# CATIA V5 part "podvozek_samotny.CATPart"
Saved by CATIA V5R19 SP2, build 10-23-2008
Part number: podvozek_samotny
Bounding box of the stored display mesh (mm): x -1700 to 1700, y -40 to 2280, z 0 to 2265.495
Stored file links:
  C:\Users\Martiin\Desktop\9.semestr\Projekt-diplomka\3D model\podvozek_samotny.CATPart
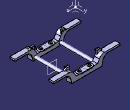
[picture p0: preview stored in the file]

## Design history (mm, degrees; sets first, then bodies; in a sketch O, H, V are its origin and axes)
Body1 (main body)
  Sketch1 on zx-plane, origin (0, 0, 0), H (-1, 0, 0), V (0, 0, 1)
    line L1 (-905.2897, 550) -> (-1700, 550)
    point P1 (-1700, 550)
    line L2 (-1700, 550) -> (-1700, 455)
    point P2 (-1700, 455)
    line L3 (-1700, 455) -> (-1111.8423, 455)
    point P3 (-770, 0)
    line L4 (-770, 0) -> (0, 0)
    line L5 (0, 220) -> (-550, 220)
    point P4 (0, 220)
    point P5 (-550, 220)
    construction line L6 (0, 66.1363) -> (0, -42.4343)
    point P6 (0, 66.1363)
    arc A1 centre (-1111.8423, 155) radius 300 from (-1111.8423, 455) to (-819.0086, 220.1801) cw
    point P8 (-1111.8423, 455)
    arc A2 centre (-905.2897, 250) radius 300 from (-905.2897, 550) to (-640.1272, 390.317) cw
    point P10 (-905.2897, 550)
    line L7 (-640.1272, 390.317) -> (-550, 220)
    point P12 (-550, 220)
    point P13 (-640.1272, 390.317)
    line L8 (-819.0086, 220.1801) -> (-770, 0)
    point P14 (-770, 0)
    point P15 (-819.0086, 220.1801)
    point P16 (1700, 550)
    point P17 (1700, 455)
    point P18 (770, 0)
    point P19 (550, 220)
    point P20 (1111.8423, 455)
    point P22 (905.2897, 550)
    point P24 (550, 220)
    point P25 (640.1272, 390.317)
    point P26 (770, 0)
    point P27 (819.0086, 220.1801)
    line L9 (905.2897, 550) -> (1700, 550)
    line L10 (1700, 550) -> (1700, 455)
    line L11 (1700, 455) -> (1111.8423, 455)
    arc A3 centre (1111.8423, 155) radius 300 from (1111.8423, 455) to (819.0086, 220.1801) ccw
    arc A4 centre (905.2897, 250) radius 300 from (905.2897, 550) to (640.1272, 390.317) ccw
    line L12 (640.1272, 390.317) -> (550, 220)
    line L13 (819.0086, 220.1801) -> (770, 0)
    point P28 (0, 220)
    line L14 (0, 220) -> (550, 220)
    point P29 (0, 0)
    line L15 (770, 0) -> (0, 0)
    line L16 (1690, 540) -> (1690, 465)
    line L17 (1690, 465) -> (1111.8423, 465)
    arc A5 centre (1111.8423, 155) radius 310 from (1111.8423, 465) to (809.2475, 222.3528) ccw
    line L18 (809.2475, 222.3528) -> (761.9811, 10)
    line L19 (761.9811, 10) -> (0, 10)
    line L20 (-761.9811, 10) -> (0, 10)
    line L21 (-809.2475, 222.3528) -> (-761.9811, 10)
    arc A6 centre (-1111.8423, 155) radius 310 from (-809.2475, 222.3528) to (-1111.8423, 465) ccw
    line L22 (-1690, 465) -> (-1111.8423, 465)
    line L23 (-1690, 540) -> (-1690, 465)
    line L24 (-905.2897, 540) -> (-1690, 540)
    arc A7 centre (-905.2897, 250) radius 290 from (-648.966, 385.6397) to (-905.2897, 540) ccw
    line L25 (-648.966, 385.6397) -> (-556.0221, 210)
    line L26 (0, 210) -> (-556.0221, 210)
    line L27 (0, 210) -> (556.0221, 210)
    line L28 (648.966, 385.6397) -> (556.0221, 210)
    arc A8 centre (905.2897, 250) radius 290 from (905.2897, 540) to (648.966, 385.6397) ccw
    line L29 (905.2897, 540) -> (1690, 540)
    distance L5 L4 = 220
    distance L6 L2 = 1700
    distance L4 L1 = 550
    distance L1 L3 = 95
    radius A1 = 300
    radius A2 = 300
    distance P14 V = 770
    distance P12 V = 550
    distance L9 L29 = 10
    horizontal: L1 H, L3 H, L4 H, L5 H
    vertical: L2 V, L6 V
    coincidence: P3 H, P4 V, P6 V, O P29, P4 P28
    tangency: A1 L3, A2 L1, L7 A2, L8 A1
    symmetry: P1 P16 V, P2 P17 V, P3 P18 V, P5 P19 V, P8 P20 V, P10 P22 V, P12 P24 V, P13 P25 V, P14 P26 V, P15 P27 V, L1 L9 V, L2 L10 V, L3 L11 V, A1 A3 V, A2 A4 V, L7 L12 V, L8 L13 V, P4 P28 V, L5 L14 V, O P29 V, L4 L15 V
  Pad1: profile Sketch1, direction (0, 1, 0), length 250
  Sketch2 on end face of Pad1, origin (0, 250, 0), H (-1, 0, 0), V (0, 0, 1)
    circle A1 centre (-650, 110) radius 85
    point P1 (-650, 110)
    reference projected line E1 (-770, 0) -> (0, 0) from edge [face of Pad1 from Sketch1.L4 | end face of Pad1]
    circle A2 centre (-650, 110) radius 70
    circle A3 centre (650, 110) radius 85
    circle A4 centre (650, 110) radius 70
    radius A1 = 85
    distance P1 E1 = 110
    distance P1 V = 650
    radius A2 = 70
    symmetry: A1 A3 V, A2 A4 V
  Pad2: profile Sketch2, direction (0, 1, 0), length 870
  Plane1: type Offset, RefPlane end face of Pad2, Offset 0, reversed
  Mirror1: of the body so far, about Plane1
  Sketch3 on end face of Pad1, origin (0, 250, 0), H (-1, 0, 0), V (0, 0, 1)
    line L1 (-865, 650) -> (-700, 650)
    line L2 (-700, 650) -> (-700, 468.7604)
    line L3 (-965, 550) -> (-865, 650)
    point P2 (-865, 650)
    reference projected line E1 (-770, 0) -> (0, 0) from edge [face of Pad1 from Sketch1.L4 | end face of Pad1]
    arc A1 centre (-905.2897, 250) radius 300 from (-700, 468.7604) to (-905.2897, 550) ccw
    reference projected arc E2 centre (-905.2897, 250) radius 300 from (-640.1272, 390.317) to (-905.2897, 550) ccw from edge [face of Mirror1 | face of Mirror1]
    line L4 (-965, 550) -> (-905.2897, 550)
    reference projected line E3 (-905.2897, 550) -> (-1700, 550) from edge [face of Mirror1 | face of Mirror1]
    angle L3 L1 = 135
    distance E1 L1 = 650
    distance L2 V = 700
    distance P2 L2 = 165
    horizontal: L1 H, L4 H
    vertical: L2 V
    coincidence: A1 E2, L4 E3
  Pad3: profile Sketch3, direction (0, -1, 0), length 70
  Sketch4 on face of Pad3 from Sketch3.L1, origin (0, 0, 650), H (1, 0, 0), V (0, 1, 0)
    construction line L1 (782.5, 324.4689) -> (782.5, 215.9945)
    point P3 (835, 250)
    line L2 (835, 250) -> (865, 250)
    line L3 (865, 250) -> (865, 300)
    line L4 (865, 300) -> (835, 300)
    line L5 (835, 300) -> (835, 250)
    point P4 (865, 250)
    point P5 (865, 300)
    point P6 (835, 300)
    reference projected line E1 (865, 250) -> (865, 180) from edge [face of Pad3 from Sketch3.L1 | face of Pad3 from Sketch3.L3]
    reference projected line E2 (700, 250) -> (780, 250) from edge [face of Pad3 from Sketch3.L1 | start face of Pad3]
    point P7 (730, 250)
    point P8 (700, 250)
    point P9 (700, 300)
    point P10 (730, 300)
    line L6 (730, 250) -> (700, 250)
    line L7 (700, 250) -> (700, 300)
    line L8 (700, 300) -> (730, 300)
    line L9 (730, 300) -> (730, 250)
    construction line L10 (850, 313.9757) -> (850, 224.2203)
    distance L4 L2 = 50
    distance L5 L3 = 30
    distance L3 L1 = 82.5
    distance L10 L3 = 15
    vertical: L1 V, L3 V, L5 V, L10 V
    horizontal: L2 H, L4 H
    coincidence: L3 E1, L2 E2
    symmetry: P3 P7 L1, P4 P8 L1, P5 P9 L1, P6 P10 L1, L2 L6 L1, L3 L7 L1, L4 L8 L1, L5 L9 L1
  Pad4: profile Sketch4, direction (0, 0, -1), length 40
  Mirror2: of Pad3, Pad4, about yz-plane
  Mirror3: of the body so far, about Plane1
  Sketch5 on face of Pad4 from Sketch4.L4, origin (848.3876, 300, 627.8501), H (1, 0, 0), V (0, 0, -1)
    point P1 (1.6124, -2.1499)
    reference projected line E1 (16.6124, -22.1499) -> (-13.3876, -22.1499) from edge [face of Pad4 from Sketch4.L4 | start face of Pad4]
    reference projected line E2 (-13.3876, -22.1499) -> (-13.3876, 17.8501) from edge [face of Pad4 from Sketch4.L4 | face of Pad4 from Sketch4.L5]
    distance P1 E1 = 20
    distance P1 E2 = 15
  Hole1: placed by Sketch5, at (850, 300, 630) direction (0, -1, 0), diameter 20, depth 30
  Sketch6 on face of Pad4 from Sketch4.L8, origin (718.7731, 300, 635.0308), H (1, 0, 0), V (0, 0, -1)
    point P1 (-3.7731, 5.0308)
    reference projected line E1 (-18.7731, -14.9692) -> (146.2269, -14.9692) from edge [face of Mirror3 | face of Mirror3]
    reference projected line E2 (-18.7731, -14.9692) -> (-18.7731, 25.0308) from edge [face of Pad4 from Sketch4.L8 | face of Pad4]
    distance P1 E1 = 20
    distance E2 P1 = 15
  Hole2: placed by Sketch6, at (715, 300, 630) direction (0, -1, 0), diameter 20, depth 30
  Sketch7 on face of Mirror2, origin (-718.919, 300, 634.1562), H (1, 0, 0), V (0, 0, -1)
    point P1 (3.919, 4.1562)
    reference projected line E1 (-11.081, -15.8438) -> (-11.081, 24.1562) from edge [face of Mirror2 | face of Mirror2]
    reference projected line E2 (-11.081, 24.1562) -> (18.919, 24.1562) from edge [face of Mirror2 | face of Mirror2]
    distance P1 E1 = 15
    distance P1 E2 = 20
  Hole3: placed by Sketch7, at (-715, 300, 630) direction (0, -1, 0), diameter 20, depth 30
  Sketch8 on face of Mirror2, origin (-843.8724, 300, 638.1702), H (1, 0, 0), V (0, 0, -1)
    point P1 (-6.1276, 8.1702)
    reference projected line E1 (-21.1276, -11.8298) -> (-21.1276, 28.1702) from edge [face of Mirror2 | face of Mirror2]
    reference projected line E2 (-21.1276, 28.1702) -> (8.8724, 28.1702) from edge [face of Mirror2 | face of Mirror2]
    distance P1 E1 = 15
    distance P1 E2 = 20
  Hole4: placed by Sketch8, at (-850, 300, 630) direction (0, -1, 0), diameter 20, depth 30
  Mirror4: of Hole1, Hole2, Hole3, Hole4, about Plane1
  Sketch9 on face of Mirror3, origin (0, 0, 10), H (1, 0, 0), V (0, 1, 0)
    point P1 (-761.9811, 10)
    line L1 (-761.9811, 10) -> (761.9811, 10)
    line L2 (761.9811, 10) -> (761.9811, 0)
    line L3 (761.9811, 0) -> (-761.9811, 0)
    line L4 (-761.9811, 0) -> (-761.9811, 10)
    point P2 (761.9811, 10)
    point P3 (761.9811, 0)
    point P4 (-761.9811, 0)
    reference projected line E1 (-761.9811, 0) -> (-761.9811, 250) from edge [face of Mirror3 | face of Mirror3]
    reference projected line E2 (0, 0) -> (-761.9811, 0) from edge [face of Mirror3 | face of Mirror3]
    reference projected line E3 (761.9811, 0) -> (761.9811, 250) from edge [face of Mirror3 | face of Mirror3]
    construction line L5 (-830, 125) -> (-480, 125)
    point P7 (0, 250)
    construction line L6 through (0, 250) direction (1, 0)
    point P10 (-761.9811, 240)
    point P11 (761.9811, 240)
    point P12 (761.9811, 250)
    point P13 (-761.9811, 250)
    line L7 (-761.9811, 240) -> (761.9811, 240)
    line L8 (761.9811, 240) -> (761.9811, 250)
    line L9 (761.9811, 250) -> (-761.9811, 250)
    line L10 (-761.9811, 250) -> (-761.9811, 240)
    distance L1 L3 = 10
    distance L5 L3 = 125
    horizontal: L1 H, L3 H, L5 H
    vertical: L2 V, L4 V
    coincidence: E1 L4, E2 L3, L2 E3
    symmetry: O P7 L5, H L6 L5, P1 P10 L5, P2 P11 L5, P3 P12 L5, P4 P13 L5, L1 L7 L5, L2 L8 L5, L3 L9 L5, L4 L10 L5
  Pad5: profile Sketch9, direction (0, 0, 1), up to the existing solid (limit type 2)
  Pad6: profile face of Pad5 from Sketch9.L8, direction along face of Pad5 from Sketch9.L8, up to the existing solid (limit type 3)
  Pad7: profile face of Pad5 from Sketch9.L2, direction along face of Pad5 from Sketch9.L2, up to the existing solid (limit type 3)
  Pad8: profile face of Pad7, direction along face of Pad7, up to the existing solid (limit type 3)
  Pad9: profile face of Pad6, direction along face of Pad6, up to the existing solid (limit type 3)
  Pad10: profile face of Pad5 from Sketch9.L4, direction along face of Pad5 from Sketch9.L4, up to the existing solid (limit type 3)
  Pad11: profile face of Pad10, direction along face of Pad10, up to the existing solid (limit type 3)
  Pad12: profile face of Pad5 from Sketch9.L10, direction along face of Pad5 from Sketch9.L10, up to the existing solid (limit type 3)
  Pad13: profile face of Pad12, direction along face of Pad12, up to the existing solid (limit type 3)
  Sketch10 on face of Mirror3, origin (0, 0, 10), H (1, 0, 0), V (0, 1, 0)
    point P1 (-761.9811, 2240)
    line L1 (-761.9811, 2240) -> (761.9811, 2240)
    line L2 (761.9811, 2240) -> (761.9811, 2230)
    line L3 (761.9811, 2230) -> (-761.9811, 2230)
    line L4 (-761.9811, 2230) -> (-761.9811, 2240)
    point P2 (761.9811, 2240)
    point P3 (761.9811, 2230)
    point P4 (-761.9811, 2230)
    reference projected line E1 (-761.9811, 2240) -> (-761.9811, 1990) from edge [face of Mirror3 | face of Mirror3]
    reference projected line E2 (761.9811, 2240) -> (761.9811, 1990) from edge [face of Mirror3 | face of Mirror3]
    reference projected line E3 (761.9811, 2240) -> (0, 2240) from edge [face of Mirror3 | face of Mirror3]
    construction line L5 (150, 2115) -> (470, 2115)
    point P7 (-761.9811, 1990)
    point P8 (761.9811, 1990)
    point P9 (761.9811, 2000)
    point P10 (-761.9811, 2000)
    line L6 (-761.9811, 1990) -> (761.9811, 1990)
    line L7 (761.9811, 1990) -> (761.9811, 2000)
    line L8 (761.9811, 2000) -> (-761.9811, 2000)
    line L9 (-761.9811, 2000) -> (-761.9811, 1990)
    distance L3 L1 = 10
    distance L5 L1 = 125
    horizontal: L1 H, L3 H, L5 H
    vertical: L2 V, L4 V
    coincidence: E1 L4, E2 L2, L1 E3
    symmetry: P1 P7 L5, P2 P8 L5, P3 P9 L5, P4 P10 L5, L1 L6 L5, L2 L7 L5, L3 L8 L5, L4 L9 L5
  Pad14: profile Sketch10, direction (0, 0, 1), up to the existing solid (limit type 3)
  Pad15: profile face of Pad14 from Sketch10.L4, direction along face of Pad14 from Sketch10.L4, up to the existing solid (limit type 3)
  Pad16: profile face of Pad15, direction along face of Pad15, up to the existing solid (limit type 3)
  Pad17: profile face of Pad14 from Sketch10.L9, direction along face of Pad14 from Sketch10.L9, up to the existing solid (limit type 3)
  Pad18: profile face of Pad17, direction along face of Pad17, up to the existing solid (limit type 3)
  Pad19: profile face of Pad14 from Sketch10.L2, direction along face of Pad14 from Sketch10.L2, up to the existing solid (limit type 3)
  Pad20: profile face of Pad14 from Sketch10.L7, direction along face of Pad14 from Sketch10.L7, up to the existing solid (limit type 3)
  Pad21: profile face of Pad19, direction along face of Pad19, up to the existing solid (limit type 3)
  Pad22: profile face of Pad20, direction along face of Pad20, up to the existing solid (limit type 3)
  Sketch11 on face of Mirror3, origin (0, 0, 220), H (1, 0, 0), V (0, 1, 0)
    arc A1 centre (250, 2115) radius 165 from (250, 1950) to (250, 2280) ccw
    point P1 (250, 2115)
    reference projected line E1 (0, 2240) -> (0, 1990) from edge [face of Mirror3 | face of Mirror3]
    reference projected line E2 (0, 2240) -> (0, 1990) from edge [face of Mirror3 | face of Mirror3]
    arc A2 centre (-250, 2115) radius 165 from (-250, 1950) to (-250, 2280) cw
    line L1 (-250, 2280) -> (250, 2280)
    line L2 (-250, 1950) -> (250, 1950)
    reference projected line E3 (0, 2240) -> (550, 2240) from edge [face of Mirror3 | face of Pad15]
    radius A1 = 165
    distance P1 E1 = 250
    distance E3 P1 = 125
    symmetry: A1 A2 E2
    tangency: L1 A2, L1 A1, L2 A1, L2 A2
  Pad23: profile Sketch11, direction (0, 0, 1), length 10
  Sketch12 on end face of Pad23, origin (0, 0, 230), H (1, 0, 0), V (0, 1, 0)
    circle A1 centre (-250, 2115) radius 75
    reference projected arc E1 centre (-250, 2115) radius 165 from (-250, 2280) to (-250, 1950) ccw from edge [face of Pad23 from Sketch11.A2 | end face of Pad23]
    radius A1 = 75
    concentricity: A1 E1
  Pad24: profile Sketch12, direction (0, 0, 1), length 10
  Sketch13 on end face of Pad24, origin (0, 0, 240), H (1, 0, 0), V (0, 1, 0)
    circle A1 centre (-250, 2115) radius 40
    reference projected circle E1 centre (-250, 2115) radius 75 from edge [face of Pad24 from Sketch12.A1 | end face of Pad24]
    radius A1 = 40
    concentricity: A1 E1
  Pad25: profile Sketch13, direction (0, 0, 1), length 60
  Mirror5: of Pad23, about Plane1
  RectPattern1: of Pad24, Pad25, direction 1 instances 2, spacing 500, along face of Mirror3 reversed, direction 2 instances 2, spacing 1990, along face of Mirror3
  DatumPoint1
  Point1: stored without definition
  Line1: stored without definition
  DatumPoint2
  Point2: type OnCurve, Support Line1, RefPoint DatumPoint2, Length -100
  AxisSystem1: origin (-450, 1209.7366, 2265.4951), X (1, 0, 0), Y (0, 1, 0), Z (0, 0, 1)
